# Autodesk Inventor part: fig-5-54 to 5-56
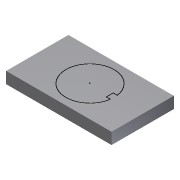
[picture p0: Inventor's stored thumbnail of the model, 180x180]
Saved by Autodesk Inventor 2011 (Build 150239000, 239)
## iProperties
Created: 2005-12
Part Number: fig-5-54 to 5-56
Document SubType Name: Modeling
Designer: CADCIM
Density: 1 g/cm^3
Author: CADCIM
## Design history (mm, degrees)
sketch "Sketch1"
  geometry: L1 (-47.674, -20.831)-(44.057, -20.831); L2 (44.057, -20.831)-(44.057, 33.398); L3 (44.057, 33.398)-(-47.674, 33.398); L4 (-47.674, 33.398)-(-47.674, -20.831)
  constraints: 8 end point, 2 parallel, 1 horizontal, 1 perpendicular
extrude "Extrusion1" new body sketch "Sketch1" distance "d0" = 10; taper "d1" = 0 deg
sketch "Sketch2"
  geometry: L1 (15.359, 9.199)-(18.885, 9.199); L2 (18.885, 3.199)-(15.359, 3.199); L3 (15.359, 3.199)-(15.359, 9.199); A1 r 20.978 centre (-1.877, 6.199) between (18.885, 9.199) and (18.885, 3.199)
  constraints: 6 end point, 2 parallel, 2 point on circle, 1 centre point, 1 horizontal, 1 vertical
body "Solid1"
